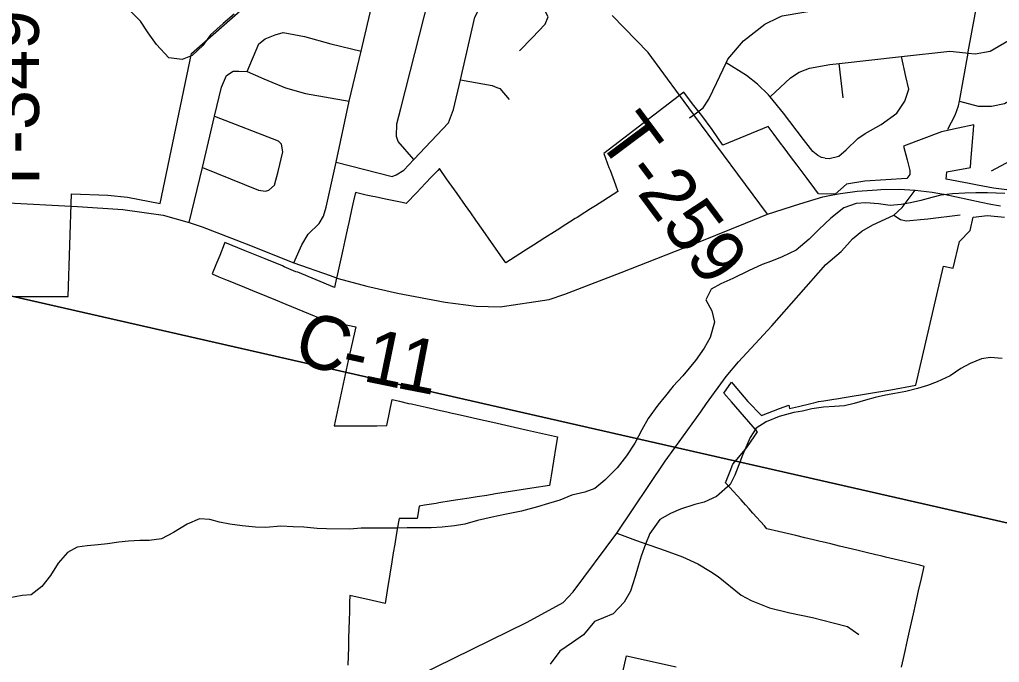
# Model space of a CAD drawing. Extents: x 114843 to 284848, y 317643 to 566895.
# Drawn here: x 179255 to 184727, y 367768 to 371355 of the extents above; entities that cross this region are included whole.
import ezdxf

# ---------------------------------------------------------------- set-up
doc = ezdxf.new("R2010")
doc.units = 0
for name, color, linetype in [('GM_X_City_Street', 7, 'Continuous'), ('GM_X_Corporation', 7, 'Continuous'), ('GM_X_County_Road', 7, 'Continuous'), ('GM_X_County_Road_Text', 7, 'Continuous'), ('GM_X_Minor_River', 7, 'Continuous'), ('GM_X_Township', 7, 'Continuous'), ('GM_X_Township_Road', 7, 'Continuous'), ('GM_X_Township_Road_Text', 7, 'Continuous')]:
    doc.layers.add(name, color=color, linetype=linetype)

msp = doc.modelspace()

# ---------------------------------------------------------------- linework, layer by layer
at = {"layer": 'GM_X_City_Street'}
for p, q in [((183853.9, 370918.6), (183833, 371110.2)), ((181023.7, 370559), (181335.9, 370479.1))]:
    msp.add_line(p, q, dxfattribs=at)
for points in [[(184439.1, 370744.2), (184480.2, 370822), (184498.9, 370873.9), (184503.7, 370900.6), (184551.6, 371168.8), (184552.9, 371176.3), (184608.4, 371476.8), (184693, 371935.3), (184694.7, 371955.8), (184702.4, 372045.6), (184695.8, 372156.1), (184659.9, 372241.9), (184656.9, 372249), (184631.3, 372283.4), (184569.8, 372336.4), (184485.9, 372387.2), (184430.6, 372420.6), (184303.3, 372498.6), (184253.9, 372557.5), (184236.7, 372619.9), (184241.5, 372686.1), (184277.9, 372858.3), (184307.3, 372966.3), (184369.1, 373184.2)], [(180786.5, 369997.7), (180830.9, 370097.7), (180866.7, 370157.3), (180928.9, 370217.1), (180953.3, 370258.5), (180966.8, 370309.5), (181023.7, 370559), (181096.1, 370900.9), (181162.3, 371178.5), (181228.3, 371455.6), (181272.5, 371636.8), (181305.8, 371711.4), (181361.1, 371796.3), (181472.7, 371875.8)], [(181335.9, 370479.1), (181357.9, 370489.4), (181401.8, 370515.9), (181456.2, 370573.8), (181649.9, 370779.6), (181679.2, 370854.2), (181717, 371018.3), (181797.8, 371369.5), (181823.4, 371419.9), (181862.1, 371457.8), (181869.1, 371464.6), (182019, 371532.5), (182086.1, 371575.6), (182323, 371728)], [(181456.2, 370573.8), (181369.8, 370674.2), (181359.5, 370702.2), (181362.6, 370774.5), (181383.8, 370859), (181566.5, 371577.7), (181598.1, 371620.2), (181643.8, 371662.9), (181709.8, 371685.7), (181763, 371700.7)], [(182047.1, 371181.5), (182118.6, 371254.5), (182190, 371329.6), (182207.6, 371369.9), (182176.8, 371427.8), (182086.1, 371575.6)], [(183446.5, 370924.9), (183560.7, 371030.9), (183609.2, 371062.4), (183665.6, 371083.7), (183780.2, 371104.3), (183833, 371110.2), (184180.9, 371149.4), (184450.7, 371179.7), (184538.8, 371170.5), (184551.6, 371168.8), (184590.9, 371163.8), (184675.2, 371178.7), (184800.5, 371251.3), (184928.8, 371412.2), (184996.3, 371515.7), (185056.9, 371545)], [(182996.9, 370807.9), (183020.4, 370824.7), (183073.4, 370862.8), (183104.1, 370910.6), (183149.4, 371004.3), (183201.5, 371113.7), (183211.2, 371133.9), (183298.7, 371237.2), (183416.2, 371330), (183493.1, 371367.2), (183513, 371376.9), (183755.5, 371417.8), (183788.3, 371423.4), (184113.5, 371457.2), (184418.6, 371489.3), (184488.8, 371490.3), (184608.4, 371476.8)], [(180525.6, 371066.5), (180592.2, 371219.8), (180626, 371248.2), (180682, 371271), (180728.1, 371283.5), (180846.9, 371260.7), (180993.9, 371220.1), (181162.3, 371178.5)], [(183753.4, 370582.7), (183775.4, 370580.4), (183829.7, 370593.8), (183870.3, 370629.4), (183937.2, 370692.7), (183977.7, 370720.3), (184066.6, 370769.3), (184153.6, 370832.3), (184198.5, 370900), (184221.5, 370968), (184204.3, 371038.4), (184180.9, 371149.4)], [(184503.7, 370900.6), (184609.2, 370872.4), (184683.3, 370871.5), (184755.7, 370886.6), (184832.4, 370931.7), (184846.7, 370940.1), (184909.2, 370976.9), (185061.1, 371095.3), (185093.7, 371137), (185124.4, 371186.8)], [(183753.4, 370582.7), (183733.4, 370585), (183713.5, 370597.3), (183685.7, 370619.8), (183632.5, 370686.7), (183522.1, 370832.7), (183446.5, 370924.9), (183437.2, 370936.2), (183375.8, 370995.3), (183314.3, 371044.2), (183201.5, 371113.7)], [(180203.2, 370224), (180275.9, 370530.8), (180343.7, 370817.2), (180382, 370978.6), (180411.4, 371043.1), (180447.3, 371067.6), (180479.4, 371068), (180525.6, 371066.5)], [(180525.6, 371066.5), (180618.5, 371025.3), (180739.6, 370974.5), (180852.5, 370943.6), (181096.1, 370900.9)], [(181717, 371018.3), (181894.6, 370987.1), (181920.8, 370977.3), (181937, 370971.5), (181989.9, 370909.8)], [(184682.7, 370512.1), (185002.8, 370682.1), (185014.4, 370688.2), (185365, 370874.4), (185487.7, 370938.7), (185492.1, 370941), (185550.5, 370960.3), (185743.7, 371013.9)], [(180343.7, 370817.2), (180698.8, 370678.9), (180717.1, 370661)], [(180647.7, 370403.3), (180679.5, 370431.8), (180698.7, 370508.2), (180725.6, 370617), (180717.1, 370661)], [(180275.9, 370530.8), (180589.5, 370402.7), (180627.7, 370397.1), (180647.7, 370403.3)]]:
    msp.add_lwpolyline(points, dxfattribs=at)
at = {"layer": 'GM_X_Corporation'}
for points in [[(179218.9, 369810.7), (179526.9, 369810.4), (179545, 370383.7), (179747.6, 370375.2), (179857.1, 370364.1), (180040.6, 370328.9), (180216.1, 371165.3), (180519.4, 371431.8)], [(184767.5, 370405.7), (184693.7, 370414.5), (184604.9, 370431.2), (184557.4, 370440.1), (184428.8, 370464.3), (184432.4, 370506.5), (184564.6, 370529.2), (184567.1, 370561.3), (184576.2, 370674.6), (184581.4, 370738.6), (184583.7, 370768.2), (184497, 370750.3), (184403.8, 370728.2), (184190.5, 370649.1), (184212.3, 370572), (184226.5, 370512.5), (184225.9, 370490.1), (184210.3, 370467.7), (183975.7, 370454.3), (183872.6, 370437.3), (183810.1, 370382.1), (183716.1, 370383.3), (183696.3, 370410.2), (183653.2, 370467.9), (183597.3, 370542.7), (183560.1, 370592.3), (183530.7, 370631.6), (183499.6, 370673.2), (183469.6, 370713.3), (183435.7, 370758.6), (183182.1, 370655.5), (183122, 370741.5), (183065.7, 370819.8), (183020.9, 370876.5), (182980.1, 370929.8), (182965.4, 370949.5), (182908.3, 370906.8), (182517.1, 370608.8), (182546.4, 370530.9), (182552.5, 370514.7), (182582.9, 370433.9), (182596.8, 370396.9), (182544.3, 370363.5), (182511.8, 370342.8), (182470.9, 370316.7), (182443.6, 370299.3), (182411.5, 370278.8), (182369.2, 370251.9), (182358.1, 370244.8), (182327, 370225), (182284.8, 370198.1), (182272.3, 370190.1), (182242.6, 370171.2), (182188.4, 370136.6), (182125.7, 370096.6), (182080.9, 370068.1), (182048.3, 370047.3), (181971.2, 369998.1), (181952.3, 370024.9), (181891.3, 370111.4), (181843.4, 370179.2), (181803.4, 370236), (181774.5, 370276.9), (181745.7, 370317.8), (181698.9, 370384.1), (181640.2, 370467.3), (181600.2, 370524), (181590.6, 370514.1), (181556.4, 370478.3), (181522.7, 370443.1), (181473.1, 370391.3), (181414, 370329.6), (181392, 370334.5), (181363.7, 370340.2), (181327.2, 370347.6), (181298.6, 370353.6), (181240.1, 370365.8), (181228.8, 370368.2), (181190.9, 370376.1), (181130.9, 370390), (181120.6, 370343.4), (181109.6, 370294.3), (181097.7, 370240.5), (181084.7, 370182), (181071.7, 370123.3), (181059.9, 370070.4), (181033.7, 369952.5), (181018.3, 369879.6), (181013.9, 369860.6), (180911.6, 369902.9), (180809.5, 369945.1), (180798.6, 369948.2), (180732.3, 369976.4), (180724, 369980.5), (180626, 370020.2), (180514.1, 370065.4), (180401.9, 370110.8), (180398.5, 370102.7), (180372.7, 370039.2), (180351.7, 369987.6), (180330.7, 369936.1), (180368.7, 369920.5), (180415, 369901.5), (180439.4, 369891.5), (180461.3, 369882.6), (180512.2, 369861.7), (180555.1, 369844.1), (180634.7, 369811.5), (180683.7, 369791.4), (180742.1, 369767.4), (180836.3, 369728.8), (180972, 369673.3), (181052.1, 369657.5), (181132.4, 369641.6), (181091.1, 369452.4), (181068.4, 369348.9), (181051.1, 369270), (181011.4, 369087.6), (181021.7, 369087.6), (181094.5, 369087.9), (181150.2, 369088.3), (181181.5, 369088.6), (181200.4, 369088.7), (181250.6, 369089.1), (181305.8, 369089.5), (181335.5, 369234.8), (181376, 369225.7), (181426.7, 369213), (181444.4, 369210.3), (181475.9, 369203.2), (181525.2, 369192.2), (181574.4, 369181.1), (181589.5, 369177.7), (181642, 369165.9), (181670.9, 369159.4), (181699.7, 369152.9), (181757.5, 369139.9), (181812.6, 369127.5), (181897.9, 369108.3), (182091.9, 369064.7), (182208.3, 369038.5), (182259.5, 369027), (182250.5, 368973.2), (182223.3, 368810.1), (182219.5, 368787.3), (182214.3, 368755.7), (182116.6, 368740.3), (181913.2, 368708.1), (181863.8, 368700.3), (181810.4, 368691.9), (181765, 368684.7), (181715.6, 368676.9), (181702.9, 368674.9), (181666.2, 368669.1), (181596.1, 368658), (181582.2, 368655.8), (181515.7, 368645.3), (181487.1, 368640.7), (181479, 368591.4), (181475.7, 368571.5), (181375.6, 368571.3), (181370.9, 368552.7), (181358.6, 368477.7), (181350.4, 368428.3), (181342.3, 368379), (181334.2, 368329.6), (181323, 368261.5), (181307.9, 368169.3), (181295.9, 368096.5), (181224.3, 368113.3), (181099.6, 368142.4), (181098.5, 368103.1), (181097.1, 368053.1), (181095.7, 368003.1), (181094.3, 367953.1), (181092.9, 367903.1), (181091.5, 367853.1), (181090.1, 367803.1), (181088.7, 367753.1)], [(184180.1, 367741.9), (184191.1, 367790.6), (184202.1, 367839.4), (184214.1, 367892.5), (184225.2, 367941.8), (184236.1, 367990.5), (184247.1, 368039.3), (184260.7, 368099.5), (184276, 368167.6), (184291.8, 368237.3), (184303, 368287.1), (184306.8, 368304.2), (184282, 368310.1), (184233.6, 368321.7), (184187.5, 368332.7), (184138.8, 368344.4), (184090.2, 368356.1), (184071.3, 368360.6), (184036.6, 368368.9), (183983.1, 368381.7), (183931.5, 368394.1), (183882.1, 368405.9), (183834.2, 368417.4), (183785.6, 368429), (183736.9, 368440.7), (183726, 368443.3), (183688.2, 368452.4), (183639.5, 368464), (183590.9, 368475.7), (183566.7, 368481.5), (183542.2, 368487.4), (183493.5, 368499), (183428.9, 368514.5), (183415.1, 368529.9), (183350.3, 368601.7), (183328.7, 368625.7), (183308.3, 368648.3), (183284.6, 368674.6), (183220.4, 368745.8), (183198, 368770.6), (183223.7, 368835.8), (183238.8, 368874), (183261.8, 368902), (183315.7, 368967.7), (183361.9, 369033.3), (183376.8, 369054.7), (183231.2, 369223.2), (183188.6, 369270.9), (183231.2, 369331.4), (183240.8, 369320), (183322.2, 369223.8), (183398.2, 369146.3), (183499.6, 369184.7), (183550.3, 369203.9), (183555.2, 369184.5), (183605.7, 369196.5), (183673.4, 369212.5), (183689.7, 369216.4), (183716.3, 369224.7), (183745.8, 369227.3), (183802.3, 369236.7), (183816.3, 369239), (183871.8, 369248.1), (184120.6, 369288.6), (184260.7, 369314.6), (184414.5, 369979.4), (184468.7, 369967.4), (184504.6, 370117.2), (184564, 370179.1), (184580.7, 370253.2), (184660.9, 370261.9), (184755, 370253.1)], [(182575.5, 367501.5), (182645.2, 367805.5), (182922.6, 367743.3)]]:
    msp.add_lwpolyline(points, dxfattribs=at)
at = {"layer": 'GM_X_County_Road'}
for points in [[(180989.3, 369927.2), (181035, 369911.3), (181193.5, 369868), (181365, 369828.5), (181631.3, 369778.6), (181804.6, 369755.5), (181939.3, 369752), (182212.3, 369792.5), (182299.6, 369822.9), (182614.9, 369944.5), (183064.9, 370120.7), (183308.8, 370219.9), (183431.7, 370270.5), (183612.2, 370327.5), (183741.2, 370366.2), (183787.4, 370374.9)], [(183787.4, 370374.9), (183828.5, 370382.7), (183838.9, 370384.2)], [(183838.9, 370384.2), (183931.8, 370397.4), (184044.5, 370404.9)], [(183878.8, 370100.6), (183906.9, 370131.8), (183958.3, 370173.9), (184020.7, 370210.1), (184136.6, 370264.6), (184184, 370306.7), (184256.9, 370403.7)], [(184044.5, 370404.9), (184065, 370406.3), (184167.3, 370410), (184256.9, 370403.7), (184351.4, 370392.4), (184413.9, 370381.9)], [(184413.9, 370381.9), (184419.1, 370381), (184624.2, 370336.7), (184678.4, 370326.1)], [(177974.2, 370214.5), (178176, 370285.4), (178491.2, 370348.7), (178754.1, 370353.2), (178840.2, 370350.6), (179472.4, 370318)], [(179472.4, 370318), (179577.8, 370312.5), (179831.3, 370296), (180056.8, 370264.1), (180203.2, 370224), (180275.5, 370199.7), (180520.2, 370104.7), (180786.5, 369997.7), (180989.3, 369927.2)], [(184678.4, 370326.1), (184721.8, 370317.6), (184732.4, 370315.3)], [(183091.9, 369212.7), (183200.4, 369363.4), (183270.6, 369445.6), (183456.9, 369646), (183757.5, 369989), (183843.8, 370061.7), (183878.8, 370100.6)], [(181067.8, 367485.8), (181081.8, 367493), (181090.5, 367497.5), (181373, 367642), (182090.1, 367992.4), (182290.4, 368102.6), (182346.5, 368162.7), (182591.3, 368490.3), (182859.7, 368890.4), (182914.5, 368966.4), (183058.7, 369166.7), (183091.9, 369212.7)]]:
    msp.add_lwpolyline(points, dxfattribs=at)
at = {"layer": 'GM_X_Minor_River'}
for points in [[(180452.7, 371385.2), (180392.4, 371333.5), (180321.9, 371269.7), (180279.5, 371209.9), (180219.1, 371154.1), (180163, 371132.4), (180089, 371142.9), (180019.4, 371215.5), (179973.8, 371282), (179930.2, 371346.4), (179874.5, 371402.9)], [(184756.5, 370385.7), (184660.5, 370388.3), (184594.4, 370388.8), (184534.4, 370387.1), (184464.3, 370383.6), (184400.3, 370375.9), (184350.1, 370362.2), (184288, 370346.6), (184229.9, 370332.9), (184177.8, 370323.2), (184117.7, 370317.6), (184051.8, 370328), (183981.8, 370332.5), (183927.7, 370328.8), (183857.5, 370305.2), (183785.1, 370247.5), (183718.7, 370183.8), (183664.3, 370130), (183591.9, 370068.3), (183513.6, 370030.7), (183453.4, 370007.1), (183401.3, 369989.4), (183325, 369953.8), (183238.7, 369910.2), (183170.5, 369880.6), (183118.2, 369850.8), (183087.8, 369790.9), (183121.5, 369730.5), (183135.1, 369666.3), (183112.5, 369582.2), (183078.1, 369522.3), (183029.7, 369452.5), (182959.1, 369366.7), (182904.7, 369308.9), (182862.3, 369255.1), (182819.9, 369203.2), (182765.4, 369129.4), (182731, 369065.5), (182690.5, 368991.5), (182644.1, 368921.7), (182591.6, 368853.8), (182523.1, 368786.1), (182466.8, 368738.4), (182412.7, 368718.7), (182338.5, 368701.1), (182272.3, 368673.5), (182208.1, 368655.8), (182148, 368636.2), (182057.8, 368612.7), (181965.6, 368593.2), (181893.5, 368579.6), (181813.3, 368560.1), (181741.2, 368540.5), (181683.1, 368530.8), (181615, 368523.3), (181553, 368519.6), (181484.9, 368520.1), (181418.9, 368518.5), (181366.8, 368516.8), (181162.7, 368518.1), (181098.7, 368512.5), (180968.6, 368513.3), (180916.6, 368515.6), (180842.6, 368522.1), (180782.6, 368524.5), (180714.6, 368528.9), (180630.5, 368521.5), (180572.5, 368523.8), (180498.5, 368530.3), (180428.5, 368538.8), (180372.5, 368551.1), (180318.6, 368565.5), (180260.6, 368569.9), (180190.4, 368540.3), (180114, 368492.6), (180047.8, 368457), (179979.7, 368449.4), (179927.7, 368447.7), (179863.6, 368444.1), (179809.5, 368438.4), (179745.5, 368430.8), (179693.4, 368425.1)], [(184742.6, 369463.7), (184676.6, 369470.1), (184626.5, 369462.4), (184564.3, 369436.7), (184512.1, 369409), (184451.8, 369367.3), (184379.6, 369333.7), (184325.4, 369314), (184269.3, 369296.3), (184205.1, 369280.6), (184143, 369269), (184091, 369259.3), (184032.8, 369245.6), (183978.7, 369232), (183916.6, 369212.3), (183862.5, 369200.6), (183806.4, 369197), (183744.4, 369193.3), (183680.3, 369183.7), (183628.1, 369170), (183578.1, 369162.3), (183497.9, 369140.8), (183423.7, 369111.2), (183369.4, 369075.5), (183335.1, 369023.6), (183292.4, 368925.6), (183272.1, 368871.6), (183249.7, 368813.6), (183223.3, 368761.6), (183146.9, 368694), (183078.6, 368662.3), (183026.5, 368648.6), (182946.3, 368623.1), (182890.1, 368599.4), (182829.9, 368565.7), (182775.3, 368487.9), (182751, 368427.9), (182726.5, 368361.9), (182710.2, 368305.9), (182693.8, 368247.8), (182667.2, 368165.8), (182630.8, 368103.9), (182570.4, 368040.1), (182516.2, 368016.4), (182466.1, 367996.7), (182403.6, 367922.9), (182343.2, 367879.2), (182272.9, 367831.5), (182218.4, 367757.7)], [(179693.4, 368425.1), (179633.3, 368419.5), (179577.3, 368411.9), (179523, 368382.1), (179470.6, 368322.3), (179428.2, 368252.4), (179379.8, 368192.6), (179319.4, 368144.9), (179269.4, 368141.2), (179191.2, 368127.6), (179109.2, 368122.1), (179047.1, 368118.5), (178963, 368109), (178907, 368103.4), (178854.9, 368095.7), (178784.7, 368076.1), (178734.4, 368034.3), (178657.9, 367960.6), (178599.7, 367932.9), (178535.5, 367901.3)]]:
    msp.add_lwpolyline(points, dxfattribs=at)
at = {"layer": 'GM_X_Township'}
for points in [[(205863.2, 363742), (199063.9, 365202.5), (198263.5, 365328.3), (198158.4, 365346.5), (195803.7, 365900.1), (193600.8, 366427), (192977.8, 366676.8), (191394.8, 367037.4), (189047.6, 367572), (188752.8, 367639.1), (188453.2, 367707.4), (188394.5, 367720.8), (187830.1, 367836), (187162.2, 368001.5), (186532.9, 368144.8), (182913.3, 368969.2), (177781.1, 370138.2)], [(177781.1, 370138.2), (182913.3, 368969.2), (186532.9, 368144.8), (187162.2, 368001.5), (187830.1, 367836), (188394.5, 367720.8), (188453.2, 367707.4), (188752.8, 367639.1), (189047.6, 367572), (191394.8, 367037.4), (192977.8, 366676.8), (193600.8, 366427), (195803.7, 365900.1), (198158.4, 365346.5), (198263.5, 365328.3), (199063.9, 365202.5), (205863.2, 363742)]]:
    msp.add_lwpolyline(points, dxfattribs=at)
at = {"layer": 'GM_X_Township_Road'}
for points in [[(182941, 370933), (182765.8, 371172.1), (182565, 371377.5)], [(183431.7, 370270.5), (183020.4, 370824.7), (183018, 370827.9), (182941, 370933)], [(184136.6, 370264.6), (184174.6, 370239.1), (184205.4, 370232.3), (184327.6, 370244.1), (184508.4, 370266.3)], [(182591.3, 368490.3), (182694, 368450.1), (182860.2, 368391.9), (182956.6, 368357.8), (183042.9, 368317.5), (183112.8, 368275), (183156, 368246.7), (183285.7, 368143.1), (183341.2, 368112.8), (183443.8, 368072.6), (183556.6, 368044.8), (183683.7, 368019.1), (183798.5, 367989.2), (183878.5, 367969.3), (183942.3, 367924.7)]]:
    msp.add_lwpolyline(points, dxfattribs=at)

# ---------------------------------------------------------------- texts
at = {"layer": 'GM_X_County_Road_Text'}
for s, rotation, p in [('C', 340.8189, (180769.5, 369459.2)), ('1', 348.3704, (181164.3, 369340.6)), ('1', 349.021, (181348.9, 369302.6)), ('-', 347.7488, (181040.4, 369367.5))]:
    msp.add_text(s, height=300, rotation=rotation, dxfattribs=at).set_placement(p)
at = {"layer": 'GM_X_Township_Road_Text'}
for s, rotation, p in [('T-349', 90.1321, (179365, 370361)), ('T-259', 306.7266, (182473.3, 370691.5))]:
    msp.add_text(s, height=300.02, rotation=rotation, dxfattribs=at).set_placement(p)

doc.saveas('drawing.dxf')
